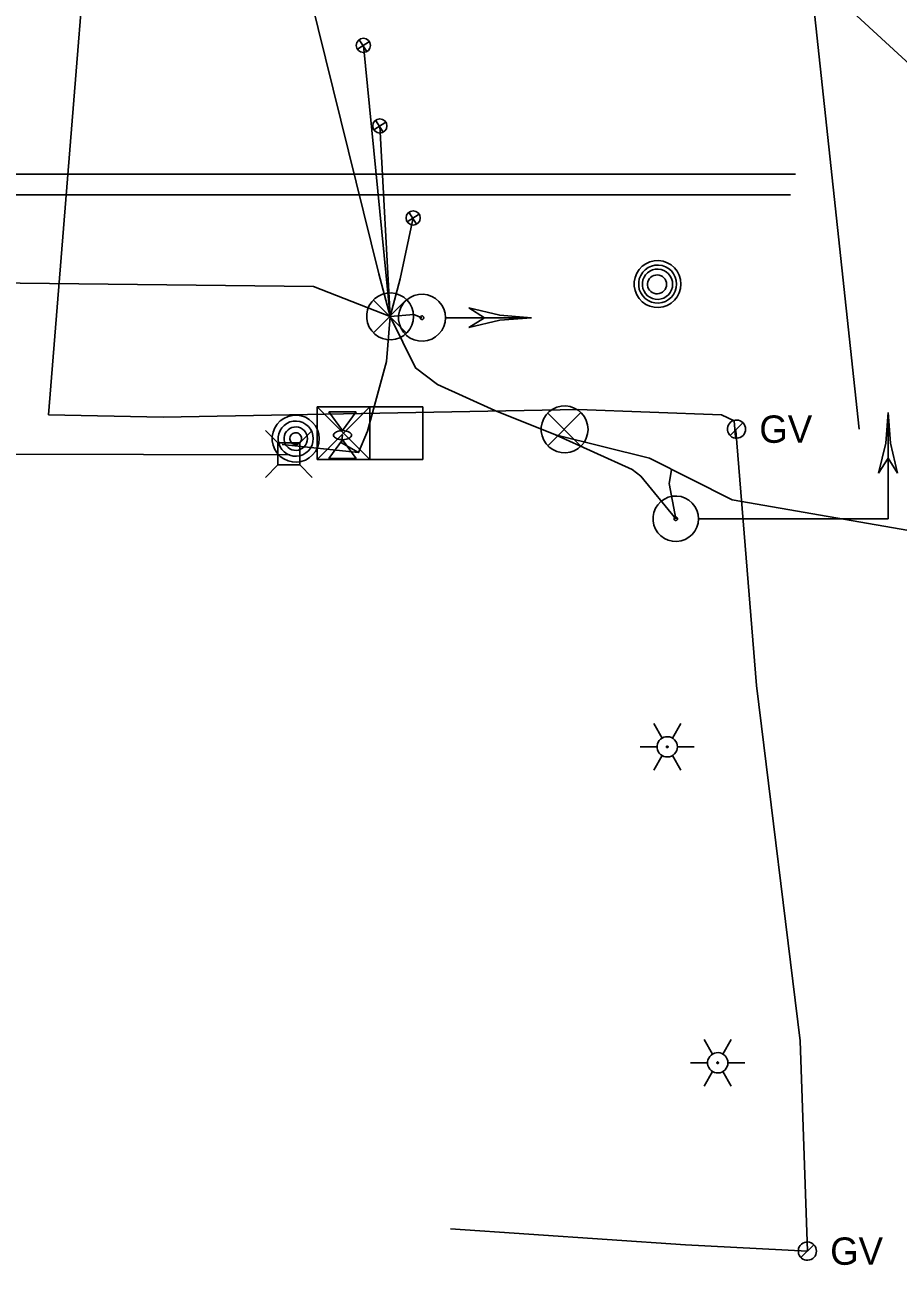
# Model space of a CAD drawing. Extents: x 596028 to 606371, y 330010 to 403088.
# Drawn here: x 604936.2 to 605059.1, y 349725.2 to 349899.9 of the extents above; entities that cross this region are included whole.
import ezdxf

# ---------------------------------------------------------------- set-up
doc = ezdxf.new("R2010")
doc.units = 0
for name, color, linetype in [('E_LTG', 7, 'Continuous'), ('E_SIG', 7, 'Continuous'), ('E_SIG_Conduit', 7, 'Continuous'), ('E_UTL_E', 7, 'Continuous'), ('E_UTL_E_Bold', 7, 'Continuous'), ('E_UTL_E_UG', 7, 'Continuous'), ('E_UTL_G', 7, 'Continuous'), ('E_UTL_G_UG', 7, 'Continuous'), ('E_UTL_Loop_UG', 7, 'Continuous'), ('E_UTL_MH', 7, 'Continuous'), ('E_UTL_Overhead', 7, 'Continuous'), ('E_UTL_T_UG', 7, 'Continuous')]:
    doc.layers.add(name, color=color, linetype=linetype)

# ---------------------------------------------------------------- blocks, each defined once
blk = doc.blocks.new('_U336')
at = {"layer": 'E_SIG'}
for p, q in [((-6.1, 0.4), (6.1, 0.4)), ((0, 6.1), (0, -6.1))]:
    blk.add_line(p, q, dxfattribs=at)
blk.add_circle((0, 0), 6.1, dxfattribs=at)
blk = doc.blocks.new('_U337')
at = {"layer": 'E_SIG'}
for p, q in [((-6.1, 0.4), (6.1, 0.4)), ((0, 6.1), (0, -6.1))]:
    blk.add_line(p, q, dxfattribs=at)
blk.add_circle((0, 0), 6.1, dxfattribs=at)
blk = doc.blocks.new('_U338')
at = {"layer": 'E_SIG'}
for p, q in [((-6.1, 0.4), (6.1, 0.4)), ((0, 6.1), (0, -6.1))]:
    blk.add_line(p, q, dxfattribs=at)
blk.add_circle((0, 0), 6.1, dxfattribs=at)
blk = doc.blocks.new('ACAD_PROXY_ENTITY_15')
at = {"layer": 'E_LTG'}
for points in [[(1843663.8, 1030159.59), (1843660.17, 1030165.87)], [(1843668.16, 1030159.59), (1843671.79, 1030165.87)], [(1843654.37, 1030155.82), (1843661.62, 1030155.82)], [(1843670.34, 1030155.82), (1843670.26, 1030156.64), (1843670.02, 1030157.44), (1843669.64, 1030158.17), (1843669.13, 1030158.82), (1843668.51, 1030159.36), (1843667.79, 1030159.78), (1843667.01, 1030160.05), (1843666.19, 1030160.17), (1843665.36, 1030160.13), (1843664.56, 1030159.93), (1843663.8, 1030159.59), (1843663.13, 1030159.11), (1843662.56, 1030158.51), (1843662.11, 1030157.81), (1843661.8, 1030157.04), (1843661.64, 1030156.23), (1843661.64, 1030155.4), (1843661.8, 1030154.59), (1843662.11, 1030153.82), (1843662.56, 1030153.12), (1843663.13, 1030152.52), (1843663.8, 1030152.04), (1843664.56, 1030151.7), (1843665.36, 1030151.51), (1843666.19, 1030151.47), (1843667.01, 1030151.58), (1843667.79, 1030151.85), (1843668.51, 1030152.27), (1843669.13, 1030152.81), (1843669.64, 1030153.46), (1843670.02, 1030154.2), (1843670.26, 1030154.99), (1843670.34, 1030155.82)], [(1843670.34, 1030155.82), (1843670.26, 1030156.64), (1843670.02, 1030157.44), (1843669.64, 1030158.17), (1843669.13, 1030158.82), (1843668.51, 1030159.36), (1843667.79, 1030159.78), (1843667.01, 1030160.05), (1843666.19, 1030160.17), (1843665.36, 1030160.13), (1843664.56, 1030159.93), (1843663.8, 1030159.59), (1843663.13, 1030159.11), (1843662.56, 1030158.51), (1843662.11, 1030157.81), (1843661.8, 1030157.04), (1843661.64, 1030156.23), (1843661.64, 1030155.4), (1843661.8, 1030154.59), (1843662.11, 1030153.82), (1843662.56, 1030153.12), (1843663.13, 1030152.52), (1843663.8, 1030152.04), (1843664.56, 1030151.7), (1843665.36, 1030151.51), (1843666.19, 1030151.47), (1843667.01, 1030151.58), (1843667.79, 1030151.85), (1843668.51, 1030152.27), (1843669.13, 1030152.81), (1843669.64, 1030153.46), (1843670.02, 1030154.2), (1843670.26, 1030154.99), (1843670.34, 1030155.82)], [(1843670.34, 1030155.82), (1843670.26, 1030156.64), (1843670.02, 1030157.44), (1843669.64, 1030158.17), (1843669.13, 1030158.82), (1843668.51, 1030159.36), (1843667.79, 1030159.78), (1843667.01, 1030160.05), (1843666.19, 1030160.17), (1843665.36, 1030160.13), (1843664.56, 1030159.93), (1843663.8, 1030159.59), (1843663.13, 1030159.11), (1843662.56, 1030158.51), (1843662.11, 1030157.81), (1843661.8, 1030157.04), (1843661.64, 1030156.23), (1843661.64, 1030155.4), (1843661.8, 1030154.59), (1843662.11, 1030153.82), (1843662.56, 1030153.12), (1843663.13, 1030152.52), (1843663.8, 1030152.04), (1843664.56, 1030151.7), (1843665.36, 1030151.51), (1843666.19, 1030151.47), (1843667.01, 1030151.58), (1843667.79, 1030151.85), (1843668.51, 1030152.27), (1843669.13, 1030152.81), (1843669.64, 1030153.46), (1843670.02, 1030154.2), (1843670.26, 1030154.99), (1843670.34, 1030155.82)], [(1843666.34, 1030155.82), (1843666.34, 1030155.88), (1843666.32, 1030155.95), (1843666.29, 1030156.01), (1843666.24, 1030156.07), (1843666.19, 1030156.11), (1843666.13, 1030156.15), (1843666.07, 1030156.17), (1843666, 1030156.18), (1843665.93, 1030156.18), (1843665.86, 1030156.16), (1843665.8, 1030156.13), (1843665.74, 1030156.09), (1843665.69, 1030156.04), (1843665.66, 1030155.98), (1843665.63, 1030155.92), (1843665.62, 1030155.85), (1843665.62, 1030155.78), (1843665.63, 1030155.71), (1843665.66, 1030155.65), (1843665.69, 1030155.59), (1843665.74, 1030155.54), (1843665.8, 1030155.5), (1843665.86, 1030155.47), (1843665.93, 1030155.46), (1843666, 1030155.45), (1843666.07, 1030155.46), (1843666.13, 1030155.49), (1843666.19, 1030155.52), (1843666.24, 1030155.57), (1843666.29, 1030155.62), (1843666.32, 1030155.68), (1843666.34, 1030155.75), (1843666.34, 1030155.82)], [(1843670.34, 1030155.82), (1843677.59, 1030155.82)], [(1843660.17, 1030145.76), (1843663.8, 1030152.04)], [(1843671.79, 1030145.76), (1843668.16, 1030152.04)]]:
    blk.add_lwpolyline(points, dxfattribs=at)

msp = doc.modelspace()

# ---------------------------------------------------------------- linework, layer by layer
at = {"layer": 'E_SIG'}
for points in [[(604990.87, 349858.81), (604990.81, 349859.44), (604990.64, 349860.04), (604990.35, 349860.6), (604989.96, 349861.09), (604989.49, 349861.5), (604988.94, 349861.81), (604988.35, 349862.02), (604987.73, 349862.11), (604987.1, 349862.08), (604986.49, 349861.93), (604985.92, 349861.67), (604985.41, 349861.31), (604984.98, 349860.85), (604984.64, 349860.32), (604984.41, 349859.74), (604984.29, 349859.13), (604984.29, 349858.5), (604984.41, 349857.88), (604984.64, 349857.3), (604984.98, 349856.77), (604985.41, 349856.32), (604985.92, 349855.95), (604986.49, 349855.69), (604987.1, 349855.55), (604987.73, 349855.52), (604988.35, 349855.61), (604988.94, 349855.81), (604989.49, 349856.12), (604989.96, 349856.54), (604990.35, 349857.03), (604990.64, 349857.59), (604990.81, 349858.19), (604990.87, 349858.81)], [(604989.83, 349861.15), (604985.22, 349856.49)], [(604985.22, 349861.1), (604989.88, 349856.45)], [(604995.36, 349858.62), (604995.3, 349859.24), (604995.12, 349859.85), (604994.83, 349860.4), (604994.44, 349860.9), (604993.97, 349861.31), (604993.43, 349861.62), (604992.83, 349861.83), (604992.21, 349861.92), (604991.59, 349861.89), (604990.98, 349861.74), (604990.41, 349861.48), (604989.89, 349861.11), (604989.46, 349860.66), (604989.12, 349860.13), (604988.89, 349859.55), (604988.77, 349858.93), (604988.77, 349858.31), (604988.89, 349857.69), (604989.12, 349857.11), (604989.46, 349856.58), (604989.89, 349856.13), (604990.41, 349855.76), (604990.98, 349855.5), (604991.59, 349855.35), (604992.21, 349855.32), (604992.83, 349855.41), (604993.43, 349855.62), (604993.97, 349855.93), (604994.44, 349856.34), (604994.83, 349856.84), (604995.12, 349857.39), (604995.3, 349858), (604995.36, 349858.62)], [(604992.31, 349858.62), (604992.3, 349858.67), (604992.29, 349858.71), (604992.27, 349858.76), (604992.24, 349858.79), (604992.2, 349858.83), (604992.16, 349858.85), (604992.12, 349858.87), (604992.07, 349858.87), (604992.02, 349858.87), (604991.97, 349858.86), (604991.93, 349858.84), (604991.89, 349858.81), (604991.86, 349858.78), (604991.83, 349858.74), (604991.81, 349858.69), (604991.8, 349858.64), (604991.8, 349858.6), (604991.81, 349858.55), (604991.83, 349858.5), (604991.86, 349858.46), (604991.89, 349858.43), (604991.93, 349858.4), (604991.97, 349858.38), (604992.02, 349858.37), (604992.07, 349858.37), (604992.12, 349858.37), (604992.16, 349858.39), (604992.2, 349858.41), (604992.24, 349858.45), (604992.27, 349858.48), (604992.29, 349858.53), (604992.3, 349858.57), (604992.31, 349858.62)], [(605000.86, 349858.62), (604998.66, 349860)], [(605007.46, 349858.62), (605003, 349858.97), (604998.66, 349859.99)], [(605007.46, 349858.62), (604995.41, 349858.62)], [(605007.46, 349858.62), (605003, 349858.27), (604998.66, 349857.24)], [(604998.66, 349857.25), (605000.86, 349858.62)], [(604977.58, 349841.6), (604977.52, 349842.22), (604977.34, 349842.82), (604977.06, 349843.38), (604976.67, 349843.87), (604976.19, 349844.28), (604975.65, 349844.6), (604975.06, 349844.8), (604974.44, 349844.89), (604973.81, 349844.86), (604973.2, 349844.71), (604972.63, 349844.45), (604972.12, 349844.09), (604971.69, 349843.64), (604971.35, 349843.11), (604971.11, 349842.53), (604970.99, 349841.91), (604970.99, 349841.28), (604971.11, 349840.67), (604971.35, 349840.08), (604971.69, 349839.56), (604972.12, 349839.1), (604972.63, 349838.74), (604973.2, 349838.48), (604973.81, 349838.33), (604974.44, 349838.3), (604975.06, 349838.39), (604975.65, 349838.59), (604976.19, 349838.91), (604976.67, 349839.32), (604977.06, 349839.81), (604977.34, 349840.37), (604977.52, 349840.97), (604977.58, 349841.6)], [(604977.31, 349838.66), (604977.31, 349846.09)], [(604977.31, 349846.09), (604992.16, 349846.09)], [(604984.74, 349846.09), (604977.31, 349838.66)], [(604977.31, 349846.09), (604984.74, 349838.66)], [(604984.74, 349838.66), (604984.74, 349846.09)], [(604992.16, 349846.09), (604992.16, 349838.66)], [(605015.43, 349842.9), (605015.37, 349843.53), (605015.19, 349844.13), (605014.91, 349844.69), (605014.52, 349845.18), (605014.04, 349845.59), (605013.5, 349845.91), (605012.91, 349846.11), (605012.29, 349846.2), (605011.66, 349846.17), (605011.05, 349846.02), (605010.48, 349845.76), (605009.97, 349845.4), (605009.53, 349844.94), (605009.2, 349844.42), (605008.96, 349843.83), (605008.84, 349843.22), (605008.84, 349842.59), (605008.96, 349841.97), (605009.2, 349841.39), (605009.53, 349840.86), (605009.97, 349840.41), (605010.48, 349840.05), (605011.05, 349839.79), (605011.66, 349839.64), (605012.29, 349839.61), (605012.91, 349839.7), (605013.5, 349839.9), (605014.04, 349840.22), (605014.52, 349840.63), (605014.91, 349841.12), (605015.19, 349841.68), (605015.37, 349842.28), (605015.43, 349842.9)], [(605014.39, 349845.24), (605009.78, 349840.58)], [(605009.78, 349845.19), (605014.43, 349840.54)], [(605057.66, 349845.27), (605057.33, 349840.95), (605056.33, 349836.73)], [(605057.66, 349830.32), (605057.66, 349845.27)], [(605057.66, 349845.27), (605058, 349840.95), (605059, 349836.73)], [(604976.75, 349841.6), (604976.71, 349842.06), (604976.58, 349842.52), (604976.36, 349842.93), (604976.07, 349843.3), (604975.72, 349843.61), (604975.31, 349843.85), (604974.86, 349844), (604974.4, 349844.07), (604973.93, 349844.05), (604973.47, 349843.94), (604973.04, 349843.74), (604972.66, 349843.47), (604972.33, 349843.13), (604972.08, 349842.73), (604971.91, 349842.29), (604971.82, 349841.83), (604971.82, 349841.36), (604971.91, 349840.9), (604972.08, 349840.46), (604972.33, 349840.07), (604972.66, 349839.73), (604973.04, 349839.45), (604973.47, 349839.26), (604973.93, 349839.15), (604974.4, 349839.12), (604974.86, 349839.19), (604975.31, 349839.34), (604975.72, 349839.58), (604976.07, 349839.89), (604976.36, 349840.26), (604976.58, 349840.68), (604976.71, 349841.13), (604976.75, 349841.6)], [(604975.93, 349841.6), (604975.9, 349841.91), (604975.81, 349842.21), (604975.67, 349842.49), (604975.47, 349842.73), (604975.24, 349842.94), (604974.97, 349843.1), (604974.67, 349843.2), (604974.36, 349843.24), (604974.05, 349843.23), (604973.74, 349843.16), (604973.45, 349843.03), (604973.2, 349842.84), (604972.98, 349842.62), (604972.81, 349842.35), (604972.7, 349842.06), (604972.64, 349841.75), (604972.64, 349841.44), (604972.7, 349841.13), (604972.81, 349840.84), (604972.98, 349840.58), (604973.2, 349840.35), (604973.45, 349840.17), (604973.74, 349840.04), (604974.05, 349839.96), (604974.36, 349839.95), (604974.67, 349839.99), (604974.97, 349840.1), (604975.24, 349840.25), (604975.47, 349840.46), (604975.67, 349840.7), (604975.81, 349840.98), (604975.9, 349841.28), (604975.93, 349841.6)], [(604975.1, 349841.6), (604975.09, 349841.75), (604975.05, 349841.9), (604974.97, 349842.04), (604974.88, 349842.17), (604974.76, 349842.27), (604974.62, 349842.35), (604974.47, 349842.4), (604974.32, 349842.42), (604974.16, 349842.41), (604974.01, 349842.38), (604973.87, 349842.31), (604973.74, 349842.22), (604973.63, 349842.11), (604973.55, 349841.97), (604973.49, 349841.83), (604973.46, 349841.67), (604973.46, 349841.52), (604973.49, 349841.36), (604973.55, 349841.22), (604973.63, 349841.09), (604973.74, 349840.97), (604973.87, 349840.88), (604974.01, 349840.82), (604974.16, 349840.78), (604974.32, 349840.77), (604974.47, 349840.79), (604974.62, 349840.85), (604974.76, 349840.92), (604974.88, 349841.03), (604974.97, 349841.15), (604975.05, 349841.29), (604975.09, 349841.44), (604975.1, 349841.6)], [(604984.74, 349842.38), (604984.74, 349842.38)], [(604992.16, 349838.66), (604977.31, 349838.66)], [(605057.66, 349838.86), (605056.33, 349836.73)], [(605059, 349836.73), (605057.66, 349838.86)], [(605030.97, 349830.32), (605030.91, 349830.93), (605030.74, 349831.51), (605030.46, 349832.05), (605030.09, 349832.53), (605029.63, 349832.93), (605029.1, 349833.24), (605028.52, 349833.43), (605027.92, 349833.52), (605027.31, 349833.49), (605026.72, 349833.35), (605026.17, 349833.1), (605025.67, 349832.74), (605025.25, 349832.3), (605024.92, 349831.79), (605024.7, 349831.22), (605024.58, 349830.63), (605024.58, 349830.02), (605024.7, 349829.42), (605024.92, 349828.85), (605025.25, 349828.34), (605025.67, 349827.9), (605026.17, 349827.55), (605026.72, 349827.3), (605027.31, 349827.15), (605027.92, 349827.12), (605028.52, 349827.21), (605029.1, 349827.41), (605029.63, 349827.71), (605030.09, 349828.11), (605030.46, 349828.59), (605030.74, 349829.13), (605030.91, 349829.72), (605030.97, 349830.32)], [(605028.01, 349830.32), (605028.01, 349830.37), (605028, 349830.41), (605027.98, 349830.45), (605027.95, 349830.49), (605027.91, 349830.52), (605027.87, 349830.54), (605027.83, 349830.56), (605027.78, 349830.57), (605027.73, 349830.56), (605027.69, 349830.55), (605027.65, 349830.53), (605027.61, 349830.51), (605027.58, 349830.47), (605027.55, 349830.43), (605027.53, 349830.39), (605027.53, 349830.35), (605027.53, 349830.3), (605027.53, 349830.25), (605027.55, 349830.21), (605027.58, 349830.17), (605027.61, 349830.14), (605027.65, 349830.11), (605027.69, 349830.09), (605027.73, 349830.08), (605027.78, 349830.08), (605027.83, 349830.08), (605027.87, 349830.1), (605027.91, 349830.12), (605027.95, 349830.15), (605027.98, 349830.19), (605028, 349830.23), (605028.01, 349830.28), (605028.01, 349830.32)], [(605057.66, 349830.32), (605031.03, 349830.32)], [(605050.19, 349830.32), (605050.19, 349830.32)]]:
    msp.add_lwpolyline(points, dxfattribs=at)
at = {"layer": 'E_SIG_Conduit'}
for points in [[(604969.92, 349929.73), (604985.98, 349864.78), (604987.57, 349858.81)], [(604741.42, 349865.71), (604976.78, 349863.03)], [(604976.78, 349863.03), (604987.57, 349858.81), (604990.92, 349859.08), (604992.06, 349858.62)], [(604987.57, 349858.81), (604987.07, 349852.47), (604984.41, 349842.64), (604983.14, 349839.65)], [(604987.57, 349858.81), (604991.15, 349851.56), (604994.26, 349849.24), (605002.31, 349845.56), (605010.87, 349842.14), (605024.06, 349838.86), (605035.73, 349832.96), (605069.52, 349827.11), (605072.1, 349826.97), (605134.18, 349822.56), (605136.25, 349822.64)], [(605010.87, 349842.14), (605021.65, 349837.24), (605022.86, 349836.32), (605027.77, 349830.32)], [(605027.77, 349830.32), (605026.86, 349835.29), (605027.19, 349837.2)]]:
    msp.add_lwpolyline(points, dxfattribs=at)
at = {"layer": 'E_UTL_E'}
for points in [[(604971.76, 349841), (604970.01, 349842.75)], [(604974.86, 349841), (604976.61, 349842.75)], [(604974.86, 349841), (604971.76, 349841)], [(604971.76, 349841), (604971.76, 349837.9)], [(604974.86, 349837.9), (604974.86, 349841)], [(604971.76, 349837.9), (604970.01, 349836.15)], [(604971.76, 349837.9), (604974.86, 349837.9)], [(604974.86, 349837.9), (604976.61, 349836.15)]]:
    msp.add_lwpolyline(points, dxfattribs=at)
at = {"layer": 'E_UTL_E_Bold'}
for points in [[(604978.97, 349845.39), (604982.78, 349845.39)], [(604980.88, 349842.72), (604978.97, 349845.39)], [(604982.78, 349845.39), (604980.88, 349842.72)], [(604980.88, 349841.45), (604978.97, 349838.79)], [(604982.15, 349842.09), (604982.12, 349842.21), (604982.05, 349842.32), (604981.94, 349842.43), (604981.79, 349842.52), (604981.61, 349842.6), (604981.4, 349842.66), (604981.17, 349842.7), (604980.94, 349842.72), (604980.69, 349842.71), (604980.46, 349842.69), (604980.24, 349842.64), (604980.04, 349842.57), (604979.88, 349842.48), (604979.75, 349842.38), (604979.66, 349842.26), (604979.61, 349842.15), (604979.61, 349842.02), (604979.66, 349841.91), (604979.75, 349841.79), (604979.88, 349841.69), (604980.04, 349841.61), (604980.24, 349841.54), (604980.46, 349841.49), (604980.69, 349841.46), (604980.94, 349841.45), (604981.17, 349841.47), (604981.4, 349841.51), (604981.61, 349841.57), (604981.79, 349841.65), (604981.94, 349841.74), (604982.05, 349841.85), (604982.12, 349841.97), (604982.15, 349842.09)], [(604982.78, 349838.79), (604980.88, 349841.45)], [(604978.97, 349838.79), (604982.78, 349838.79)]]:
    msp.add_lwpolyline(points, dxfattribs=at)
at = {"layer": 'E_UTL_E_UG'}
msp.add_line((604884.24, 349839.48), (604973.44, 349839.32), dxfattribs=at)
msp.add_lwpolyline([(604980.88, 349842.09), (604980.73, 349840.99), (604983.14, 349839.65), (604972.37, 349840.79)], dxfattribs=at)
at = {"layer": 'E_UTL_G'}
for points in [[(605037.61, 349842.94), (605037.59, 349843.18), (605037.52, 349843.41), (605037.41, 349843.63), (605037.26, 349843.82), (605037.07, 349843.98), (605036.86, 349844.1), (605036.63, 349844.18), (605036.39, 349844.22), (605036.15, 349844.21), (605035.91, 349844.15), (605035.69, 349844.05), (605035.49, 349843.91), (605035.32, 349843.73), (605035.19, 349843.52), (605035.1, 349843.3), (605035.05, 349843.06), (605035.05, 349842.81), (605035.1, 349842.57), (605035.19, 349842.35), (605035.32, 349842.14), (605035.49, 349841.97), (605035.69, 349841.82), (605035.91, 349841.72), (605036.15, 349841.67), (605036.39, 349841.65), (605036.63, 349841.69), (605036.86, 349841.77), (605037.07, 349841.89), (605037.26, 349842.05), (605037.41, 349842.24), (605037.52, 349842.46), (605037.59, 349842.69), (605037.61, 349842.94)], [(605035.42, 349842.03), (605037.24, 349843.84)], [(605047.59, 349727.22), (605047.56, 349727.47), (605047.5, 349727.7), (605047.38, 349727.92), (605047.23, 349728.11), (605047.05, 349728.27), (605046.84, 349728.39), (605046.61, 349728.47), (605046.36, 349728.51), (605046.12, 349728.49), (605045.88, 349728.44), (605045.66, 349728.33), (605045.46, 349728.19), (605045.3, 349728.02), (605045.16, 349727.81), (605045.07, 349727.59), (605045.03, 349727.35), (605045.03, 349727.1), (605045.07, 349726.86), (605045.16, 349726.64), (605045.3, 349726.43), (605045.46, 349726.25), (605045.66, 349726.11), (605045.88, 349726.01), (605046.12, 349725.95), (605046.36, 349725.94), (605046.61, 349725.98), (605046.84, 349726.06), (605047.05, 349726.18), (605047.23, 349726.34), (605047.38, 349726.53), (605047.5, 349726.75), (605047.56, 349726.98), (605047.59, 349727.22)], [(605045.4, 349726.32), (605047.21, 349728.13)]]:
    msp.add_lwpolyline(points, dxfattribs=at)
at = {"layer": 'E_UTL_G_UG'}
for points in [[(605053.61, 349842.94), (605039.42, 349974.87)], [(604939.48, 349844.93), (604948.15, 349952.82)], [(604939.48, 349844.93), (604955.62, 349844.62), (605014.04, 349845.69), (605034.23, 349844.97), (605036.01, 349844.09), (605036.2, 349841.8)], [(604996.09, 349730.36), (605029.14, 349728.11), (605046.3, 349727.22), (605045.31, 349756.83), (605039.16, 349806.86), (605037.85, 349823.07), (605036.21, 349842.73)]]:
    msp.add_lwpolyline(points, dxfattribs=at)
at = {"layer": 'E_UTL_Loop_UG'}
for points in [[(604987.57, 349858.81), (604983.81, 349896.95)], [(604987.57, 349858.81), (604986.12, 349885.62)], [(604987.57, 349858.81), (604988.97, 349864.07), (604990.82, 349872.67)]]:
    msp.add_lwpolyline(points, dxfattribs=at)
at = {"layer": 'E_UTL_MH'}
for points in [[(605028.51, 349863.36), (605028.45, 349863.99), (605028.28, 349864.59), (605027.99, 349865.15), (605027.6, 349865.64), (605027.13, 349866.05), (605026.58, 349866.36), (605025.99, 349866.57), (605025.37, 349866.66), (605024.74, 349866.63), (605024.13, 349866.48), (605023.56, 349866.22), (605023.05, 349865.86), (605022.62, 349865.4), (605022.28, 349864.87), (605022.05, 349864.29), (605021.93, 349863.68), (605021.93, 349863.05), (605022.05, 349862.43), (605022.28, 349861.85), (605022.62, 349861.32), (605023.05, 349860.87), (605023.56, 349860.5), (605024.13, 349860.24), (605024.74, 349860.1), (605025.37, 349860.07), (605025.99, 349860.16), (605026.58, 349860.36), (605027.13, 349860.67), (605027.6, 349861.09), (605027.99, 349861.58), (605028.28, 349862.14), (605028.45, 349862.74), (605028.51, 349863.36)], [(605027.9, 349863.36), (605027.85, 349863.86), (605027.71, 349864.35), (605027.47, 349864.81), (605027.16, 349865.21), (605026.77, 349865.54), (605026.33, 349865.79), (605025.85, 349865.96), (605025.35, 349866.03), (605024.84, 349866.01), (605024.35, 349865.89), (605023.88, 349865.68), (605023.47, 349865.38), (605023.12, 349865.01), (605022.84, 349864.58), (605022.65, 349864.11), (605022.56, 349863.61), (605022.56, 349863.1), (605022.65, 349862.6), (605022.84, 349862.13), (605023.12, 349861.7), (605023.47, 349861.34), (605023.88, 349861.04), (605024.35, 349860.83), (605024.84, 349860.71), (605025.35, 349860.68), (605025.85, 349860.76), (605026.33, 349860.92), (605026.77, 349861.18), (605027.16, 349861.51), (605027.47, 349861.91), (605027.71, 349862.36), (605027.85, 349862.85), (605027.9, 349863.36)], [(605027.34, 349863.33), (605027.3, 349863.73), (605027.18, 349864.12), (605027, 349864.48), (605026.75, 349864.8), (605026.44, 349865.06), (605026.09, 349865.27), (605025.71, 349865.4), (605025.31, 349865.46), (605024.9, 349865.44), (605024.51, 349865.34), (605024.14, 349865.17), (605023.81, 349864.94), (605023.53, 349864.65), (605023.31, 349864.31), (605023.16, 349863.93), (605023.09, 349863.53), (605023.09, 349863.13), (605023.16, 349862.73), (605023.31, 349862.35), (605023.53, 349862.01), (605023.81, 349861.72), (605024.14, 349861.49), (605024.51, 349861.32), (605024.9, 349861.22), (605025.31, 349861.2), (605025.71, 349861.26), (605026.09, 349861.39), (605026.44, 349861.6), (605026.75, 349861.86), (605027, 349862.18), (605027.18, 349862.54), (605027.3, 349862.93), (605027.34, 349863.33)], [(605026.48, 349863.31), (605026.46, 349863.57), (605026.38, 349863.81), (605026.27, 349864.03), (605026.11, 349864.23), (605025.92, 349864.4), (605025.7, 349864.53), (605025.46, 349864.61), (605025.21, 349864.64), (605024.96, 349864.63), (605024.71, 349864.57), (605024.48, 349864.47), (605024.28, 349864.32), (605024.1, 349864.14), (605023.96, 349863.92), (605023.87, 349863.69), (605023.82, 349863.44), (605023.82, 349863.19), (605023.87, 349862.94), (605023.96, 349862.7), (605024.1, 349862.49), (605024.28, 349862.31), (605024.48, 349862.16), (605024.71, 349862.06), (605024.96, 349862), (605025.21, 349861.98), (605025.46, 349862.02), (605025.7, 349862.1), (605025.92, 349862.23), (605026.11, 349862.39), (605026.27, 349862.59), (605026.38, 349862.82), (605026.46, 349863.06), (605026.48, 349863.31)]]:
    msp.add_lwpolyline(points, dxfattribs=at)
at = {"layer": 'E_UTL_Overhead'}
msp.add_line((604968.54, 349979.07), (605141.52, 349819.92), dxfattribs=at)
at = {"layer": 'E_UTL_T_UG'}
for p, q in [((604990.59, 349878.82), (605044.64, 349878.82)), ((604989.88, 349875.93), (605043.93, 349875.93))]:
    msp.add_line(p, q, dxfattribs=at)
for points in [[(604648.72, 349878.82), (604990.59, 349878.82)], [(604651.26, 349875.93), (604989.88, 349875.93)]]:
    msp.add_lwpolyline(points, dxfattribs=at)

# ---------------------------------------------------------------- block references
at = {"layer": 'E_LTG', "xscale": 0.32808333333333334, "yscale": 0.32808333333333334}
for p in [(150.5, 11821.26), (157.6, 11776.78)]:
    msp.add_blockref('ACAD_PROXY_ENTITY_15', p, dxfattribs=at)
at = {"layer": 'E_SIG_Conduit', "xscale": 0.16404166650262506, "yscale": 0.16404166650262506, "rotation": 122.69997330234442}
for name, p in [('_U337', (604986.12, 349885.62)), ('_U338', (604990.82, 349872.67))]:
    msp.add_blockref(name, p, dxfattribs=at)
at = {"layer": 'E_UTL_Loop_UG', "xscale": 0.16404166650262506, "yscale": 0.16404166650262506, "rotation": 122.69997330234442}
msp.add_blockref('_U336', (604983.81, 349896.95), dxfattribs=at)

# ---------------------------------------------------------------- texts
at = {"layer": 'E_UTL_G'}
for p in [(605039.54, 349841.01), (605049.51, 349725.3)]:
    msp.add_text('GV', height=3.85, dxfattribs=at).set_placement(p)

doc.saveas('drawing.dxf')
